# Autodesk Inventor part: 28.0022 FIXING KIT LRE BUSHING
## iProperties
Created: 2007-04
Part Number: 28.0022 FIXING KIT LRE BUSHING
Document SubType Name: Modeling
Designer: Andy Moles
Material: Steel
Mass: 20.1742 g
Surface Area: 23.0035 cm^2
Volume: 2.56997 cm^3
Density: 7.85 g/cm^3
Author: Andy Moles
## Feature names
1. Extrusion1
2. Extrusion2
3. Extrusion3
4. Extrusion4
5. Hole1
